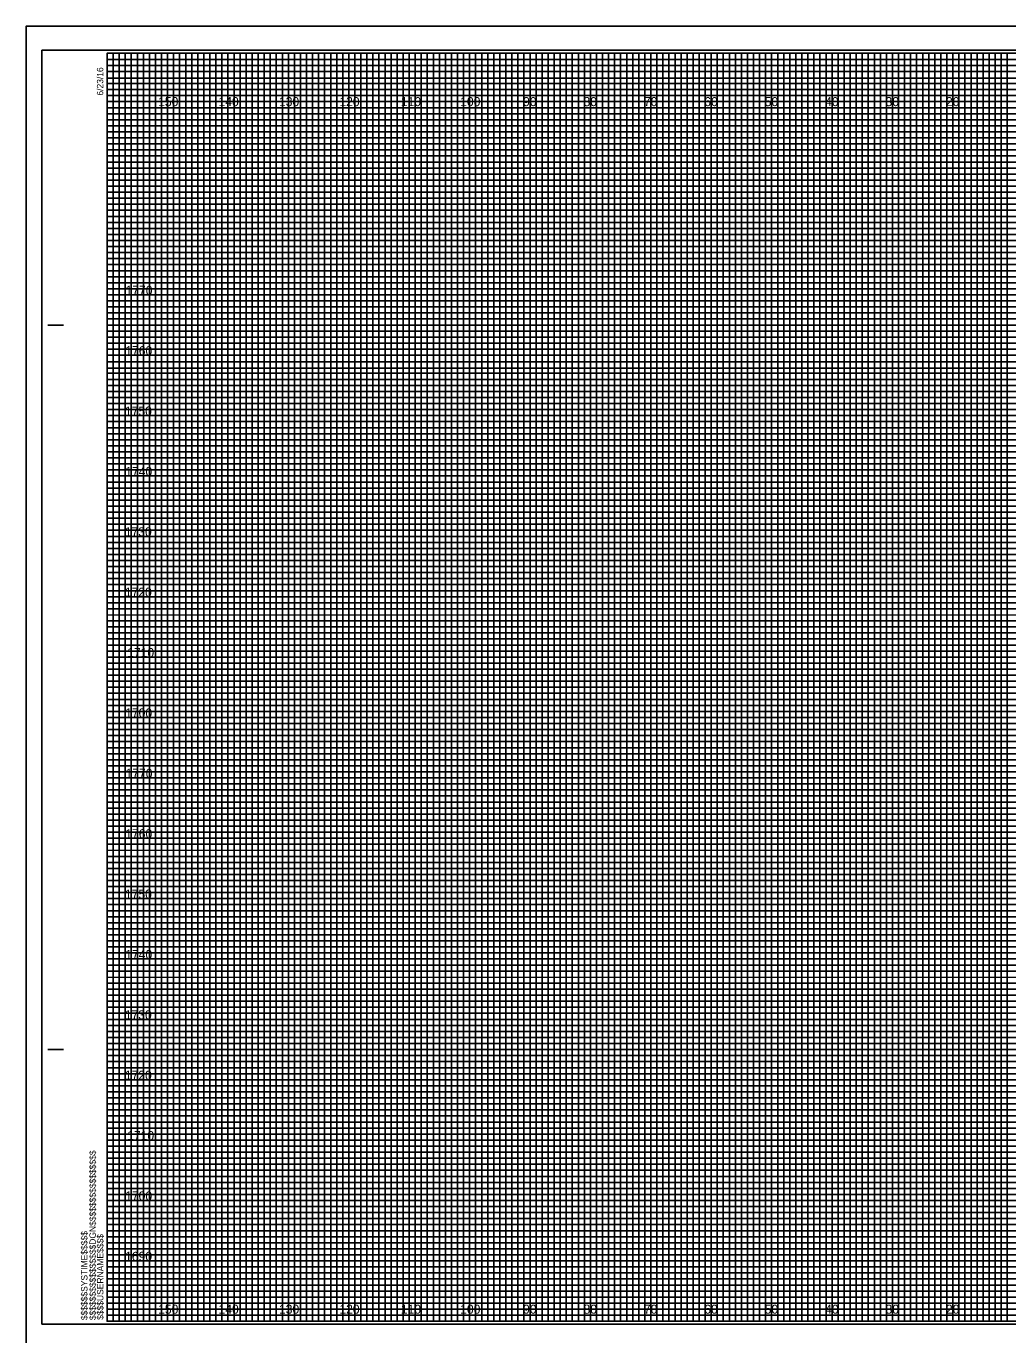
# Model space of a CAD drawing. Extents: x -13 to 1780, y -15 to 3284.
# Drawn here: x 1443.3 to 1605.8, y 647.5 to 864.2 of the extents above; entities that cross this region are included whole.
import ezdxf

# ---------------------------------------------------------------- set-up
doc = ezdxf.new("R2010")
doc.units = 0
for name, color, linetype in [('Prop Retaining Wall', 7, 'Continuous'), ('Prop SS Cut Line', 7, 'Continuous'), ('Prop SS Fill Line', 7, 'Continuous'), ('Prop SS Transition Line', 7, 'Continuous'), ('Prop XS Earthwork Shape', 7, 'Continuous'), ('Prop XS Noise Wall', 7, 'Continuous'), ('Prop XS Station Labels', 7, 'Continuous'), ('Raster_Level_0', 7, 'Continuous'), ('Scratch_Level_3', 7, 'Continuous'), ('Scratch_Level_7', 7, 'Continuous'), ('Typical Bridge Rail CELL', 7, 'Continuous')]:
    doc.layers.add(name, color=color, linetype=linetype)

msp = doc.modelspace()

# ---------------------------------------------------------------- linework, layer by layer
at = {"layer": 'Prop Retaining Wall'}
for p, q in [((1446.88, 814.71), (1449.38, 814.71)), ((1446.98, 814.71), (1449.48, 814.71)), ((1446.88, 694.71), (1449.38, 694.71)), ((1446.98, 694.71), (1449.48, 694.71)), ((1456.68, 649.71), (1456.68, 649.71)), ((1456.68, 649.71), (1456.68, 649.71)), ((1456.68, 649.71), (1456.68, 649.71)), ((1456.68, 649.71), (1456.68, 649.71)), ((1456.68, 649.71), (1456.68, 649.71)), ((1456.68, 649.71), (1456.68, 649.71)), ((1456.68, 649.71), (1456.68, 649.71))]:
    msp.add_line(p, q, dxfattribs=at)
msp.add_lwpolyline([(1776.68, 859.71), (1456.68, 859.71), (1456.68, 649.71), (1776.68, 649.71)], close=True, dxfattribs=at)
at = {"layer": 'Prop SS Cut Line'}
for points in [[(1456.68, 859.71), (1461.68, 859.71), (1461.68, 649.71), (1471.68, 649.71), (1471.68, 859.71), (1481.68, 859.71), (1481.68, 649.71), (1491.68, 649.71), (1491.68, 859.71), (1501.68, 859.71), (1501.68, 649.71), (1511.68, 649.71), (1511.68, 859.71), (1521.68, 859.71), (1521.68, 649.71), (1531.68, 649.71), (1531.68, 859.71), (1541.68, 859.71), (1541.68, 649.71), (1551.68, 649.71), (1551.68, 859.71), (1561.68, 859.71), (1561.68, 649.71), (1571.68, 649.71), (1571.68, 859.71), (1581.68, 859.71), (1581.68, 649.71), (1591.68, 649.71), (1591.68, 859.71), (1601.68, 859.71), (1601.68, 649.71), (1611.68, 649.71)], [(1456.68, 854.71), (1731.68, 854.71)], [(1456.68, 834.71), (1776.68, 834.71), (1776.68, 844.71), (1456.68, 844.71)], [(1456.68, 814.71), (1776.68, 814.71), (1776.68, 824.71), (1456.68, 824.71)], [(1456.68, 794.71), (1776.68, 794.71), (1776.68, 804.71), (1456.68, 804.71)], [(1456.68, 774.71), (1776.68, 774.71), (1776.68, 784.71), (1456.68, 784.71)], [(1456.68, 754.71), (1776.68, 754.71), (1776.68, 764.71), (1456.68, 764.71)], [(1456.68, 734.71), (1776.68, 734.71), (1776.68, 744.71), (1456.68, 744.71)], [(1456.68, 714.71), (1776.68, 714.71), (1776.68, 724.71), (1456.68, 724.71)], [(1456.68, 694.71), (1776.68, 694.71), (1776.68, 704.71), (1456.68, 704.71)], [(1456.68, 674.71), (1776.68, 674.71), (1776.68, 684.71), (1456.68, 684.71)], [(1456.68, 654.71), (1776.68, 654.71), (1776.68, 664.71), (1456.68, 664.71)]]:
    msp.add_lwpolyline(points, dxfattribs=at)
at = {"layer": 'Prop SS Fill Line'}
for p, q in [((1466.68, 859.71), (1456.68, 859.71)), ((1466.68, 649.71), (1466.68, 859.71)), ((1486.68, 859.71), (1476.68, 859.71)), ((1476.68, 859.71), (1476.68, 649.71)), ((1486.68, 649.71), (1486.68, 859.71)), ((1506.68, 859.71), (1496.68, 859.71)), ((1496.68, 859.71), (1496.68, 649.71)), ((1506.68, 649.71), (1506.68, 859.71)), ((1526.68, 859.71), (1516.68, 859.71)), ((1516.68, 859.71), (1516.68, 649.71)), ((1526.68, 649.71), (1526.68, 859.71)), ((1546.68, 859.71), (1536.68, 859.71)), ((1536.68, 859.71), (1536.68, 649.71)), ((1546.68, 649.71), (1546.68, 859.71)), ((1566.68, 859.71), (1556.68, 859.71)), ((1556.68, 859.71), (1556.68, 649.71)), ((1566.68, 649.71), (1566.68, 859.71)), ((1586.68, 859.71), (1576.68, 859.71)), ((1576.68, 859.71), (1576.68, 649.71)), ((1586.68, 649.71), (1586.68, 859.71)), ((1606.68, 859.71), (1596.68, 859.71)), ((1596.68, 859.71), (1596.68, 649.71)), ((1476.68, 649.71), (1466.68, 649.71)), ((1496.68, 649.71), (1486.68, 649.71)), ((1516.68, 649.71), (1506.68, 649.71)), ((1536.68, 649.71), (1526.68, 649.71)), ((1556.68, 649.71), (1546.68, 649.71)), ((1576.68, 649.71), (1566.68, 649.71)), ((1596.68, 649.71), (1586.68, 649.71))]:
    msp.add_line(p, q, dxfattribs=at)
for points in [[(1456.68, 849.71), (1776.68, 849.71), (1776.68, 839.71), (1456.68, 839.71)], [(1456.68, 829.71), (1776.68, 829.71), (1776.68, 819.71), (1456.68, 819.71)], [(1456.68, 809.71), (1776.68, 809.71), (1776.68, 799.71), (1456.68, 799.71)], [(1456.68, 789.71), (1776.68, 789.71), (1776.68, 779.71), (1456.68, 779.71)], [(1456.68, 769.71), (1776.68, 769.71), (1776.68, 759.71), (1456.68, 759.71)], [(1456.68, 749.71), (1776.68, 749.71), (1776.68, 739.71), (1456.68, 739.71)], [(1456.68, 729.71), (1776.68, 729.71), (1776.68, 719.71), (1456.68, 719.71)], [(1456.68, 709.71), (1776.68, 709.71), (1776.68, 699.71), (1456.68, 699.71)], [(1456.68, 689.71), (1776.68, 689.71), (1776.68, 679.71), (1456.68, 679.71)], [(1456.68, 669.71), (1776.68, 669.71), (1776.68, 659.71), (1456.68, 659.71)]]:
    msp.add_lwpolyline(points, dxfattribs=at)
at = {"layer": 'Prop SS Transition Line'}
for p, q in [((1456.68, 858.71), (1716.68, 858.71)), ((1716.68, 857.69), (1456.68, 857.69)), ((1456.68, 857.69), (1456.68, 856.71)), ((1456.68, 856.71), (1716.68, 856.71)), ((1716.68, 855.6), (1456.68, 855.6)), ((1456.68, 855.6), (1456.68, 853.71)), ((1456.68, 853.71), (1776.68, 853.71))]:
    msp.add_line(p, q, dxfattribs=at)
for points in [[(1456.68, 852.71), (1726.68, 852.71), (1776.68, 852.71), (1776.68, 851.71), (1456.68, 851.71)], [(1456.68, 850.71), (1776.68, 850.71), (1776.68, 848.71), (1456.68, 848.71)], [(1456.68, 847.71), (1776.68, 847.71), (1776.68, 846.71), (1456.68, 846.69)], [(1456.68, 845.71), (1776.68, 845.71), (1776.68, 843.71), (1456.68, 843.71)], [(1456.68, 842.71), (1776.68, 842.71), (1776.68, 841.71), (1456.68, 841.71)], [(1456.68, 840.71), (1776.68, 840.71), (1776.68, 838.71), (1456.68, 838.71)], [(1456.68, 837.71), (1776.68, 837.71), (1776.68, 836.71), (1456.68, 836.71)], [(1456.68, 835.71), (1776.68, 835.71), (1776.68, 833.71), (1456.68, 833.71)], [(1456.68, 832.71), (1776.68, 832.71), (1776.68, 831.71), (1456.68, 831.71)], [(1456.68, 830.71), (1776.68, 830.71), (1776.68, 828.71), (1456.68, 828.71)], [(1456.68, 827.71), (1776.68, 827.71), (1776.68, 826.71), (1456.68, 826.71)], [(1456.68, 825.71), (1776.68, 825.71), (1776.68, 823.66), (1776.68, 822.71), (1776.68, 821.71), (1456.68, 821.71)], [(1456.68, 823.71), (1776.68, 823.71), (1776.68, 822.71), (1456.68, 822.71)], [(1456.68, 820.71), (1776.68, 820.71), (1776.68, 818.71), (1456.68, 818.74)], [(1456.68, 818.74), (1776.68, 818.71), (1776.68, 817.71), (1456.68, 817.71)], [(1456.68, 816.71), (1776.68, 816.71), (1776.68, 815.71), (1456.68, 815.71)], [(1456.68, 813.71), (1776.68, 813.71), (1776.68, 812.71), (1456.68, 812.71)], [(1456.68, 811.71), (1776.68, 811.71), (1776.68, 810.71), (1456.68, 810.71)], [(1456.61, 808.6), (1776.68, 808.6), (1776.68, 807.59), (1456.61, 807.59)], [(1456.68, 806.71), (1776.68, 806.71), (1776.68, 805.71), (1456.68, 805.71)], [(1456.68, 803.71), (1776.68, 803.71), (1776.68, 802.71), (1456.68, 802.71)], [(1456.68, 801.71), (1776.68, 801.71), (1776.68, 800.71), (1456.68, 800.71)], [(1456.68, 798.71), (1776.68, 798.71), (1776.68, 797.71), (1456.68, 797.71)], [(1456.68, 796.71), (1776.68, 796.71), (1776.68, 795.71), (1456.68, 795.71)], [(1456.68, 793.71), (1776.68, 793.71), (1776.68, 792.71), (1456.68, 792.71)], [(1456.68, 791.71), (1776.68, 791.71), (1776.68, 790.71), (1456.68, 790.71)], [(1456.68, 788.71), (1776.68, 788.71), (1776.67, 787.69), (1456.68, 787.71)], [(1456.68, 786.71), (1776.68, 786.71), (1776.68, 785.71), (1456.68, 785.71)], [(1456.68, 783.71), (1776.68, 783.71), (1776.68, 782.71), (1456.68, 782.71)], [(1456.68, 781.71), (1776.68, 781.71), (1776.68, 780.71), (1456.68, 780.71)], [(1456.68, 778.71), (1776.68, 778.71), (1776.68, 777.71), (1456.68, 777.71)], [(1456.68, 776.71), (1776.68, 776.71), (1776.68, 775.71), (1456.68, 775.71)], [(1456.68, 773.71), (1776.68, 773.71), (1776.68, 772.71), (1456.68, 772.71)], [(1456.68, 771.71), (1776.68, 771.71), (1776.68, 770.71), (1456.68, 770.71)], [(1456.68, 768.71), (1776.68, 768.71), (1776.68, 767.71), (1456.68, 767.71)], [(1456.68, 766.7), (1776.75, 766.62), (1776.68, 765.71), (1456.68, 765.71)], [(1456.68, 763.71), (1776.68, 763.71), (1776.68, 762.71), (1456.68, 762.71)], [(1456.68, 761.71), (1776.68, 761.71), (1776.68, 760.71), (1456.68, 760.71)], [(1456.68, 758.71), (1776.68, 758.71), (1776.68, 757.71), (1456.68, 757.71)], [(1456.68, 756.71), (1776.68, 756.71), (1776.68, 755.71), (1456.68, 755.71)], [(1456.68, 753.71), (1776.68, 753.71), (1776.68, 752.71), (1456.68, 752.71)], [(1456.68, 751.71), (1776.68, 751.71), (1776.68, 750.71), (1456.68, 750.71)], [(1456.68, 748.71), (1776.68, 748.71), (1776.68, 747.71), (1456.68, 747.71)], [(1456.68, 746.71), (1776.68, 746.71), (1776.68, 745.71), (1456.68, 745.71)], [(1456.68, 743.71), (1776.68, 743.71), (1776.68, 742.71), (1456.68, 742.71)], [(1456.68, 741.71), (1776.68, 741.71), (1776.68, 740.71), (1456.68, 740.71)], [(1456.68, 738.71), (1776.68, 738.71), (1776.68, 737.71), (1456.68, 737.71)], [(1456.68, 736.71), (1776.68, 736.71), (1776.68, 735.71), (1456.68, 735.71)], [(1456.68, 733.71), (1776.68, 733.71), (1776.68, 732.71), (1456.68, 732.71)], [(1456.68, 731.71), (1776.68, 731.71), (1776.68, 730.71), (1456.68, 730.71)], [(1456.68, 728.71), (1776.68, 728.71), (1776.67, 727.69), (1456.68, 727.71)], [(1456.68, 726.71), (1776.68, 726.71), (1776.68, 725.71), (1456.68, 725.71)], [(1456.68, 723.71), (1776.68, 723.71), (1776.68, 722.71), (1456.68, 722.71)], [(1456.68, 721.71), (1776.68, 721.71), (1776.68, 720.71), (1456.68, 720.71)], [(1456.68, 718.71), (1776.68, 718.71), (1776.68, 717.71), (1456.68, 717.71)], [(1456.68, 716.71), (1776.68, 716.71), (1776.68, 715.71), (1456.68, 715.71)], [(1456.68, 713.71), (1776.68, 713.71), (1776.68, 712.71), (1456.68, 712.71)], [(1456.68, 711.71), (1776.68, 711.71), (1776.68, 710.71), (1456.68, 710.71)], [(1456.68, 708.71), (1776.68, 708.71), (1776.68, 707.71), (1456.68, 707.71)], [(1456.68, 706.7), (1776.75, 706.62), (1776.68, 705.71), (1456.68, 705.71)], [(1456.68, 703.71), (1776.68, 703.71), (1776.68, 702.71), (1456.68, 702.71)], [(1456.68, 701.71), (1776.68, 701.71), (1776.68, 700.71), (1456.68, 700.71)], [(1456.68, 698.71), (1776.68, 698.71), (1776.68, 697.71), (1456.68, 697.71)], [(1456.68, 696.71), (1776.68, 696.71), (1776.68, 695.71), (1456.68, 695.71)], [(1456.68, 693.71), (1776.68, 693.71), (1776.68, 692.71), (1456.68, 692.71)], [(1456.68, 691.71), (1776.68, 691.71), (1776.68, 690.71), (1456.68, 690.71)], [(1456.68, 688.71), (1776.68, 688.71), (1776.68, 687.71), (1456.68, 687.71)], [(1456.68, 686.71), (1776.68, 686.71), (1776.68, 685.71), (1456.68, 685.71)], [(1456.68, 683.71), (1776.68, 683.71), (1776.68, 682.71), (1456.68, 682.71)], [(1456.68, 681.71), (1776.68, 681.71), (1776.68, 680.71), (1456.68, 680.71)], [(1456.68, 678.71), (1776.68, 678.71), (1776.68, 677.71), (1456.68, 677.71)], [(1456.68, 676.71), (1776.68, 676.71), (1776.68, 675.71), (1456.68, 675.71)], [(1456.68, 673.71), (1776.68, 673.71), (1776.68, 672.71), (1456.68, 672.71)], [(1456.68, 671.71), (1776.68, 671.71), (1776.68, 670.71), (1456.68, 670.71)], [(1456.68, 668.71), (1776.68, 668.71), (1776.68, 667.71), (1456.68, 667.71)], [(1456.68, 666.71), (1776.68, 666.71), (1776.68, 665.71), (1456.68, 665.71)], [(1456.68, 663.71), (1776.68, 663.71), (1776.68, 662.71), (1456.68, 662.71)], [(1456.68, 661.71), (1776.68, 661.71), (1776.68, 660.71), (1456.68, 660.71)], [(1456.68, 658.71), (1776.68, 658.71), (1776.68, 657.71), (1456.68, 657.71)], [(1456.68, 656.71), (1776.68, 656.71), (1776.68, 655.71), (1456.68, 655.71)], [(1456.68, 653.71), (1776.68, 653.71), (1776.68, 652.71), (1456.68, 652.71)], [(1456.68, 651.71), (1776.68, 651.71), (1776.68, 650.71), (1456.68, 650.71)]]:
    msp.add_lwpolyline(points, dxfattribs=at)
at = {"layer": 'Prop XS Earthwork Shape'}
msp.add_lwpolyline([(1443.28, 645.21), (1779.98, 645.21), (1779.98, 864.21), (1443.28, 864.21)], close=True, dxfattribs=at)
at = {"layer": 'Prop XS Noise Wall'}
for p, q in [((1466.68, 649.71), (1466.68, 859.71)), ((1476.68, 649.71), (1476.68, 859.71)), ((1486.68, 649.71), (1486.68, 859.71)), ((1496.68, 649.71), (1496.68, 859.71)), ((1506.68, 649.71), (1506.68, 859.71)), ((1516.68, 649.71), (1516.68, 859.71)), ((1526.68, 649.71), (1526.68, 859.71)), ((1536.68, 649.71), (1536.68, 859.71)), ((1546.68, 649.71), (1546.68, 859.71)), ((1556.68, 649.71), (1556.68, 859.71)), ((1566.68, 649.71), (1566.68, 859.71)), ((1576.68, 649.71), (1576.68, 859.71)), ((1586.68, 649.71), (1586.68, 859.71)), ((1596.68, 649.71), (1596.68, 859.71)), ((1456.68, 849.71), (1776.68, 849.71)), ((1456.68, 839.71), (1776.68, 839.71)), ((1456.68, 829.71), (1776.68, 829.71)), ((1456.68, 819.71), (1776.68, 819.71)), ((1456.68, 809.71), (1776.68, 809.71)), ((1456.68, 799.71), (1776.68, 799.71)), ((1456.68, 789.71), (1776.68, 789.71)), ((1456.68, 779.71), (1776.68, 779.71)), ((1456.68, 769.71), (1776.68, 769.71)), ((1456.68, 759.71), (1776.68, 759.71)), ((1456.68, 749.71), (1776.68, 749.71)), ((1456.68, 739.71), (1776.68, 739.71)), ((1456.68, 729.71), (1776.68, 729.71)), ((1456.68, 719.71), (1776.68, 719.71)), ((1456.68, 709.71), (1776.68, 709.71)), ((1456.68, 699.71), (1776.68, 699.71)), ((1456.68, 689.71), (1776.68, 689.71)), ((1456.68, 679.71), (1776.68, 679.71)), ((1456.68, 669.71), (1776.68, 669.71)), ((1456.68, 659.71), (1776.68, 659.71))]:
    msp.add_line(p, q, dxfattribs=at)
at = {"layer": 'Prop XS Station Labels'}
for p, q in [((1779.98, 864.21), (1443.28, 864.21)), ((1443.28, 864.21), (1443.28, 645.21))]:
    msp.add_line(p, q, dxfattribs=at)
at = {"layer": 'Scratch_Level_7'}
msp.add_lwpolyline([(1445.88, 649.21), (1779.08, 649.21), (1779.08, 860.21), (1445.88, 860.21)], close=True, dxfattribs=at)
at = {"layer": 'Typical Bridge Rail CELL'}
for points in [[(1456.68, 649.71), (1457.68, 649.71), (1457.68, 859.71), (1458.68, 859.71), (1458.68, 649.71)], [(1458.68, 649.71), (1459.68, 649.71), (1459.68, 859.71), (1460.68, 859.71), (1460.68, 649.71)], [(1461.68, 649.71), (1462.68, 649.71), (1462.68, 859.71), (1463.68, 859.71), (1463.68, 649.71)], [(1463.68, 649.71), (1464.68, 649.71), (1464.68, 859.71), (1465.68, 859.71), (1465.68, 649.71)], [(1466.68, 649.71), (1467.68, 649.71), (1467.68, 859.71), (1468.68, 859.71), (1468.68, 649.71)], [(1468.68, 649.71), (1469.68, 649.71), (1469.68, 859.71), (1470.68, 859.71), (1470.68, 649.71)], [(1471.68, 649.71), (1472.68, 649.71), (1472.68, 859.71), (1473.68, 859.71), (1473.68, 649.71)], [(1473.68, 649.71), (1474.68, 649.71), (1474.68, 859.71), (1475.68, 859.71), (1475.68, 649.71)], [(1476.68, 649.71), (1477.68, 649.71), (1477.68, 859.71), (1478.68, 859.71), (1478.68, 649.71)], [(1478.68, 649.71), (1479.68, 649.71), (1479.68, 859.71), (1480.68, 859.71), (1480.68, 649.71)], [(1481.68, 649.71), (1482.68, 649.71), (1482.68, 859.71), (1483.68, 859.71), (1483.68, 649.71)], [(1483.68, 649.71), (1484.68, 649.71), (1484.68, 859.71), (1485.68, 859.71), (1485.68, 649.71)], [(1486.68, 649.71), (1487.68, 649.71), (1487.68, 859.71), (1488.68, 859.71), (1488.68, 649.71)], [(1488.68, 649.71), (1489.68, 649.71), (1489.68, 859.71), (1490.68, 859.71), (1490.68, 649.71)], [(1491.68, 649.71), (1492.68, 649.71), (1492.68, 859.71), (1493.68, 859.71), (1493.68, 649.71)], [(1493.68, 649.71), (1494.68, 649.71), (1494.68, 859.71), (1495.68, 859.71), (1495.68, 649.71)], [(1496.68, 649.71), (1497.68, 649.71), (1497.68, 859.71), (1498.68, 859.71), (1498.68, 649.71)], [(1498.68, 649.71), (1499.68, 649.71), (1499.68, 859.71), (1500.68, 859.71), (1500.68, 649.71)], [(1501.68, 649.71), (1502.68, 649.71), (1502.68, 859.71), (1503.68, 859.71), (1503.68, 649.71)], [(1503.68, 649.71), (1504.68, 649.71), (1504.68, 859.71), (1505.68, 859.71), (1505.68, 649.71)], [(1506.68, 649.71), (1507.68, 649.71), (1507.68, 859.71), (1508.68, 859.71), (1508.68, 649.71)], [(1508.68, 649.71), (1509.68, 649.71), (1509.68, 859.71), (1510.68, 859.71), (1510.68, 649.71)], [(1511.68, 649.71), (1512.68, 649.71), (1512.68, 859.71), (1513.68, 859.71), (1513.68, 649.71)], [(1513.68, 649.71), (1514.68, 649.71), (1514.68, 859.71), (1515.68, 859.71), (1515.68, 649.71)], [(1516.68, 649.71), (1517.68, 649.71), (1517.68, 859.71), (1518.68, 859.71), (1518.68, 649.71)], [(1518.68, 649.71), (1519.68, 649.71), (1519.68, 859.71), (1520.68, 859.71), (1520.68, 649.71)], [(1521.68, 649.71), (1522.68, 649.71), (1522.68, 859.71), (1523.68, 859.71), (1523.68, 649.71)], [(1523.68, 649.71), (1524.68, 649.71), (1524.68, 859.71), (1525.68, 859.71), (1525.68, 649.71)], [(1526.68, 649.71), (1527.68, 649.71), (1527.68, 859.71), (1528.68, 859.71), (1528.68, 649.71)], [(1528.68, 649.71), (1529.68, 649.71), (1529.68, 859.71), (1530.68, 859.71), (1530.68, 649.71)], [(1531.68, 649.71), (1532.68, 649.71), (1532.68, 859.71), (1533.68, 859.71), (1533.68, 649.71)], [(1533.68, 649.71), (1534.68, 649.71), (1534.68, 859.71), (1535.68, 859.71), (1535.68, 649.71)], [(1536.68, 649.71), (1537.68, 649.71), (1537.68, 859.71), (1538.68, 859.71), (1538.68, 649.71)], [(1538.68, 649.71), (1539.68, 649.71), (1539.68, 859.71), (1540.68, 859.71), (1540.68, 649.71)], [(1541.68, 649.71), (1542.68, 649.71), (1542.68, 859.71), (1543.68, 859.71), (1543.68, 649.71)], [(1543.68, 649.71), (1544.68, 649.71), (1544.68, 859.71), (1545.68, 859.71), (1545.68, 649.71)], [(1546.68, 649.71), (1547.68, 649.71), (1547.68, 859.71), (1548.68, 859.71), (1548.68, 649.71)], [(1548.68, 649.71), (1549.68, 649.71), (1549.68, 859.71), (1550.68, 859.71), (1550.68, 649.71)], [(1551.68, 649.71), (1552.68, 649.71), (1552.68, 859.71), (1553.68, 859.71), (1553.68, 649.71)], [(1553.68, 649.71), (1554.68, 649.71), (1554.68, 859.71), (1555.68, 859.71), (1555.68, 649.71)], [(1556.68, 649.71), (1557.68, 649.71), (1557.68, 859.71), (1558.68, 859.71), (1558.68, 649.71)], [(1558.68, 649.71), (1559.68, 649.71), (1559.68, 859.71), (1560.68, 859.71), (1560.68, 649.71)], [(1561.68, 649.71), (1562.68, 649.71), (1562.68, 859.71), (1563.68, 859.71), (1563.68, 649.71)], [(1563.68, 649.71), (1564.68, 649.71), (1564.68, 859.71), (1565.68, 859.71), (1565.68, 649.71)], [(1566.68, 649.71), (1567.68, 649.71), (1567.68, 859.71), (1568.68, 859.71), (1568.68, 649.71)], [(1568.68, 649.71), (1569.68, 649.71), (1569.68, 859.71), (1570.68, 859.71), (1570.68, 649.71)], [(1571.68, 649.71), (1572.68, 649.71), (1572.68, 859.71), (1573.68, 859.71), (1573.68, 649.71)], [(1573.68, 649.71), (1574.68, 649.71), (1574.68, 859.71), (1575.68, 859.71), (1575.68, 649.71)], [(1576.68, 649.71), (1577.68, 649.71), (1577.68, 859.71), (1578.68, 859.71), (1578.68, 649.71)], [(1578.68, 649.71), (1579.68, 649.71), (1579.68, 859.71), (1580.68, 859.71), (1580.68, 649.71)], [(1581.68, 649.71), (1582.68, 649.71), (1582.68, 859.71), (1583.68, 859.71), (1583.68, 649.71)], [(1583.68, 649.71), (1584.68, 649.71), (1584.68, 859.71), (1585.68, 859.71), (1585.68, 649.71)], [(1586.68, 649.71), (1587.68, 649.71), (1587.68, 859.71), (1588.68, 859.71), (1588.68, 649.71)], [(1588.68, 649.71), (1589.68, 649.71), (1589.68, 859.71), (1590.68, 859.71), (1590.68, 649.71)], [(1591.68, 649.71), (1592.68, 649.71), (1592.68, 859.71), (1593.68, 859.71), (1593.68, 649.71)], [(1593.68, 649.71), (1594.68, 649.71), (1594.68, 859.71), (1595.68, 859.71), (1595.68, 649.71)], [(1596.68, 649.71), (1597.68, 649.71), (1597.68, 859.71), (1598.68, 859.71), (1598.68, 649.71)], [(1598.68, 649.71), (1599.68, 649.71), (1599.68, 859.71), (1600.68, 859.71), (1600.68, 649.71)], [(1601.68, 649.71), (1602.68, 649.71), (1602.68, 859.71), (1603.68, 859.71), (1603.68, 649.71)], [(1603.68, 649.71), (1604.68, 649.71), (1604.68, 859.71), (1605.68, 859.71), (1605.68, 649.71)]]:
    msp.add_lwpolyline(points, dxfattribs=at)

# ---------------------------------------------------------------- texts
at = {"layer": 'Prop Retaining Wall'}
for s, p in [('6/23/16', (1456.03, 852.71)), ('$$$$$$$$$$$$$$$$DGN$$$$$$$$$$$$$$$$', (1454.8, 649.89)), ('$$$$$$SYSTIME$$$$$', (1453.42, 649.89)), ('$$$$USERNAME$$$$', (1456.06, 649.94))]:
    msp.add_text(s, height=1.05, rotation=90, dxfattribs=at).set_placement(p)
at = {"layer": 'Raster_Level_0'}
for s, p in [('150', (1465.12, 850.96)), ('140', (1475.12, 850.96)), ('130', (1485.12, 850.96)), ('120', (1495.12, 850.96)), ('110', (1505.3, 850.96)), ('100', (1515.12, 850.96)), ('90', (1525.53, 850.96)), ('80', (1535.53, 850.96)), ('70', (1545.53, 850.96)), ('60', (1555.53, 850.96)), ('50', (1565.53, 850.96)), ('40', (1575.53, 850.96)), ('30', (1585.53, 850.96)), ('20', (1595.53, 850.96)), ('150', (1465.12, 650.96)), ('140', (1475.12, 650.96)), ('130', (1485.12, 650.96)), ('120', (1495.12, 650.96)), ('110', (1505.3, 650.96)), ('100', (1515.12, 650.96)), ('90', (1525.53, 650.96)), ('80', (1535.53, 650.96)), ('70', (1545.53, 650.96)), ('60', (1555.53, 650.96)), ('50', (1565.53, 650.96)), ('40', (1575.53, 650.96)), ('30', (1585.53, 650.96)), ('20', (1595.53, 650.96))]:
    msp.add_text(s, height=1.5, dxfattribs=at).set_placement(p)
at = {"layer": 'Scratch_Level_3'}
for s, p in [('1770', (1459.72, 819.71)), ('1760', (1459.68, 809.71)), ('1750', (1459.63, 799.71)), ('1740', (1459.68, 789.71)), ('1730', (1459.6, 779.71)), ('1720', (1459.61, 769.71)), ('1710', (1459.99, 759.71)), ('1700', (1459.66, 749.71)), ('1770', (1459.72, 739.71)), ('1760', (1459.68, 729.71)), ('1750', (1459.63, 719.71)), ('1740', (1459.68, 709.71)), ('1730', (1459.6, 699.71)), ('1720', (1459.61, 689.71)), ('1710', (1459.99, 679.71)), ('1700', (1459.66, 669.71)), ('1690', (1459.65, 659.71))]:
    msp.add_text(s, height=1.5, dxfattribs=at).set_placement(p)

doc.saveas('drawing.dxf')
